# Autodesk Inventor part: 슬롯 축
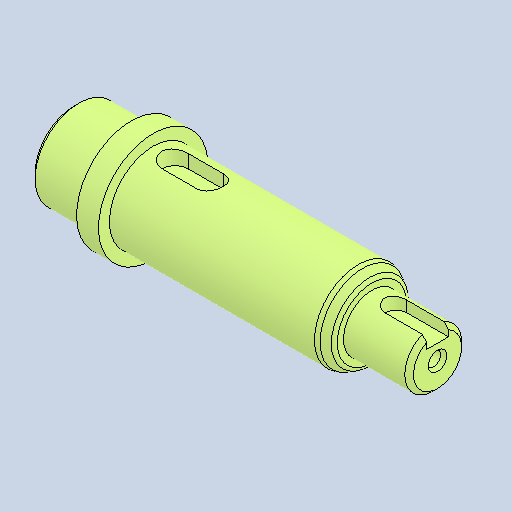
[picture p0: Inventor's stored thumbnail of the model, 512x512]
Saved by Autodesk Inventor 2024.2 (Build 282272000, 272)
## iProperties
Created: 2025-09
Part Number: 슬롯 축
Material: 강철, 탄소
Document SubType Name: Modeling
Designer: home
Density: 7.85 g/cm^3
Appearance: 기본값
Author: jhkim
Sending System: Autodesk Inventor 2026
Preprocessor: ST-DEVELOPER v20.1
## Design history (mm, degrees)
feature "솔리드1"
node "솔리드2"
